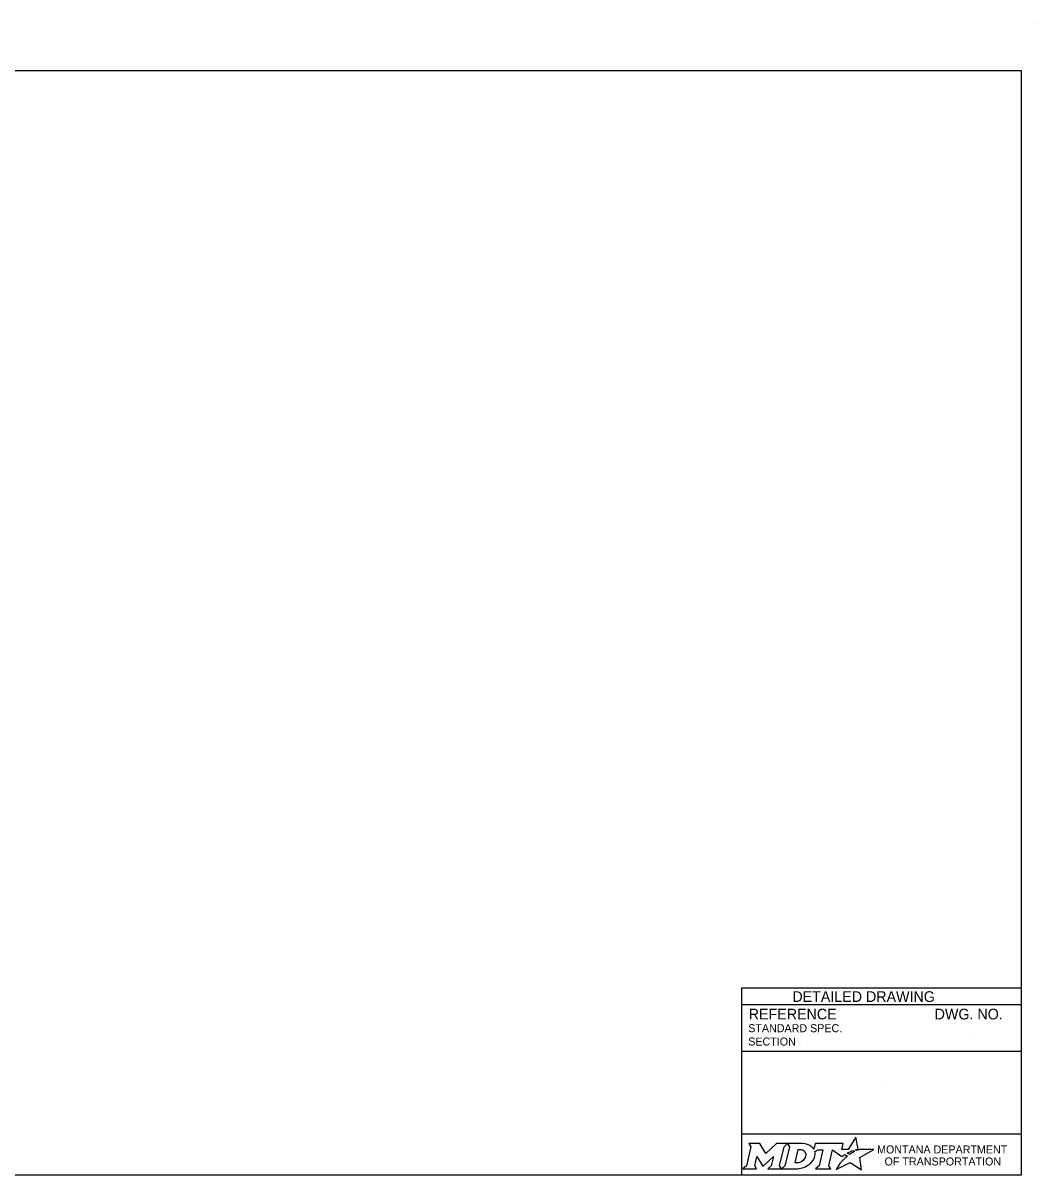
# Model space of a CAD drawing. Extents: x 49991.4 to 50021, y 49987.6 to 50011.4.
# Drawn here: x 50013.45 to 50021.04, y 49999.89 to 50008.52 of the extents above; entities that cross this region are included whole.
import ezdxf

# ---------------------------------------------------------------- set-up
doc = ezdxf.new("R2010")
doc.units = 0
for name, color, linetype in [('Default', 7, 'Continuous'), ('Level 1', 7, 'Continuous'), ('Level 4', 7, 'Continuous')]:
    doc.layers.add(name, color=color, linetype=linetype)

msp = doc.modelspace()

# ---------------------------------------------------------------- linework, layer by layer
at = {"layer": 'Default'}
for points in [[(50018.8933, 50000.1206), (50018.9074, 50000.0972), (50018.8739, 49999.9539), (50018.8482, 49999.9314), (50018.9498, 49999.9314), (50018.9363, 49999.9542), (50018.9525, 50000.0243), (50018.9962, 49999.9553), (50019.0015, 49999.9553), (50019.0766, 50000.0248), (50019.0602, 49999.9537), (50019.0355, 49999.9317), (50019.1371, 49999.9317), (50019.1233, 49999.955), (50019.1565, 50000.0974)], [(50019.1565, 50000.0974), (50019.1818, 50000.1206), (50019.0994, 50000.1206), (50019.0198, 50000.0476), (50018.9753, 50000.1203), (50018.8933, 50000.1206)], [(50019.2954, 50000.1206), (50019.1818, 50000.1206), (50019.1965, 50000.0977), (50019.1626, 49999.9539), (50019.1371, 49999.9317), (50019.2477, 49999.9317)], [(50019.7003, 50000.0679), (50019.69, 50000.0735), (50019.7016, 50000.0763), (50019.7132, 50000.0783), (50019.6958, 50000.1684), (50019.6363, 50000.0771), (50019.589, 50000.0764), (50019.5993, 50000.1205), (50019.3901, 50000.1206), (50019.38, 50000.0781), (50019.3742, 50000.0864)], [(50019.3194, 50000.0339), (50019.3182, 50000.0258), (50019.315, 50000.0165), (50019.3108, 50000.0083), (50019.3052, 50000.0008), (50019.2987, 49999.9939), (50019.2908, 49999.9876), (50019.2825, 49999.9829), (50019.2734, 49999.979), (50019.2643, 49999.9767), (50019.2551, 49999.9758), (50019.2392, 49999.9758), (50019.2628, 50000.0758), (50019.2788, 50000.0758), (50019.2864, 50000.0752), (50019.294, 50000.0733), (50019.3006, 50000.0703), (50019.3067, 50000.0661), (50019.3115, 50000.0611), (50019.3152, 50000.0551), (50019.3179, 50000.0489), (50019.3195, 50000.0415), (50019.3195, 50000.0385), (50019.3194, 50000.0339)], [(50019.3868, 50000.0615), (50019.4114, 50000.0746), (50019.4483, 50000.0746), (50019.4197, 49999.9541), (50019.3922, 49999.9314), (50019.5084, 49999.9314), (50019.4914, 49999.9543), (50019.5196, 50000.0745), (50019.5909, 50000.0228), (50019.612, 50000.0379), (50019.6317, 50000.027)], [(50019.5759, 49999.9711), (50019.5606, 49999.9467), (50019.5559, 49999.9392), (50019.5501, 49999.9306), (50019.5478, 49999.9263), (50019.6531, 49999.9794), (50019.737, 49999.9243), (50019.7239, 50000.017), (50019.8308, 50000.0754), (50019.7815, 50000.0762), (50019.7514, 50000.0766), (50019.7306, 50000.0769), (50019.7238, 50000.0754), (50019.7189, 50000.0742), (50019.7105, 50000.0719), (50019.7003, 50000.0679)], [(50019.6499, 50000.0403), (50019.6475, 50000.0386), (50019.6292, 50000.0482), (50019.6395, 50000.0539), (50019.6436, 50000.0561), (50019.6522, 50000.0601), (50019.6579, 50000.0627), (50019.6658, 50000.0657), (50019.6731, 50000.0684), (50019.6849, 50000.061), (50019.6809, 50000.0589), (50019.6763, 50000.0564), (50019.6721, 50000.0542), (50019.6671, 50000.0513), (50019.6652, 50000.0502), (50019.6625, 50000.0486), (50019.66, 50000.0472), (50019.6577, 50000.0456), (50019.6551, 50000.0438), (50019.6524, 50000.042), (50019.6499, 50000.0403)], [(50019.2934, 49999.939), (50019.3018, 49999.9416), (50019.3148, 49999.947), (50019.3352, 49999.958)], [(50019.5898, 49999.9872), (50019.5898, 49999.9872)]]:
    msp.add_lwpolyline(points, dxfattribs=at)
for centre, radius, start, end in [((50019.3185, 50000.0422), 0.0709, 339.53292, 15.85821), ((50019.2745, 50000.0595), 0.1183, 300.91025, 339.13831)]:
    msp.add_arc(centre, radius, start, end, dxfattribs=at)
for centre, major_axis, ratio, start_param, end_param in [((50019.2933, 50000.0732), (0.0834, -0.0037), 0.568097, 0.61298, 1.570796), ((50019.3489, 50000.0805), (0.0361, -0.0295), 0.469099, 1.225588, 1.570796), ((50019.6206, 50000.0173), (-0.0112, -0.0097), 0.021651, 3.157348, 6.283185), ((50019.5829, 49999.9791), (-0.00694, -0.00806), 0.008222, 0, 3.137361), ((50019.5996, 49999.9974), (-0.0098, -0.0102), 0.016458, 3.141593, 6.279097), ((50019.248, 50000.08), (0, 0.1484), 0.987302, 3.139398, 3.456847)]:
    msp.add_ellipse(centre, major_axis=major_axis, ratio=ratio, start_param=start_param, end_param=end_param, dxfattribs=at)
at = {"layer": 'Level 1'}
msp.add_line((50021.0378, 50008.5236), (50021.0378, 50008.5236), dxfattribs=at)
msp.add_lwpolyline([(50020.9378, 50008.1646), (50009.7374, 50008.1646), (50009.7374, 49999.8856), (50020.9378, 49999.8856)], close=True, dxfattribs=at)
at = {"layer": 'Level 4'}
for p, q in [((50020.9378, 50001.2856), (50018.8378, 50001.2856)), ((50018.8378, 50001.2856), (50018.8378, 49999.8856)), ((50020.9378, 50001.1606), (50018.8378, 50001.1606)), ((50020.5739, 50000.9455), (50020.5739, 50000.9455)), ((50020.9378, 50000.8106), (50018.8378, 50000.8106)), ((50019.3321, 50000.8861), (50019.3321, 50000.8861)), ((50019.8878, 50000.5615), (50019.8878, 50000.5615)), ((50020.9378, 50000.1925), (50018.8378, 50000.1925))]:
    msp.add_line(p, q, dxfattribs=at)

# ---------------------------------------------------------------- texts
at = {"layer": 'Default'}
for s, p in [('MONTANA DEPARTMENT', (50019.854, 50000.0468)), ('OF TRANSPORTATION', (50019.9102, 49999.9568))]:
    msp.add_text(s, height=0.06, dxfattribs=at).set_placement(p)
at = {"layer": 'Level 4'}
for s, height, p in [('DETAILED DRAWING', 0.0799, (50019.2188, 50001.1831)), ('REFERENCE', 0.08, (50018.8914, 50001.0522)), ('DWG. NO.', 0.08, (50020.2856, 50001.0522)), ('STANDARD SPEC.', 0.06, (50018.8881, 50000.9562)), ('SECTION', 0.06, (50018.8881, 50000.8562))]:
    msp.add_text(s, height=height, dxfattribs=at).set_placement(p)

doc.saveas('drawing.dxf')
